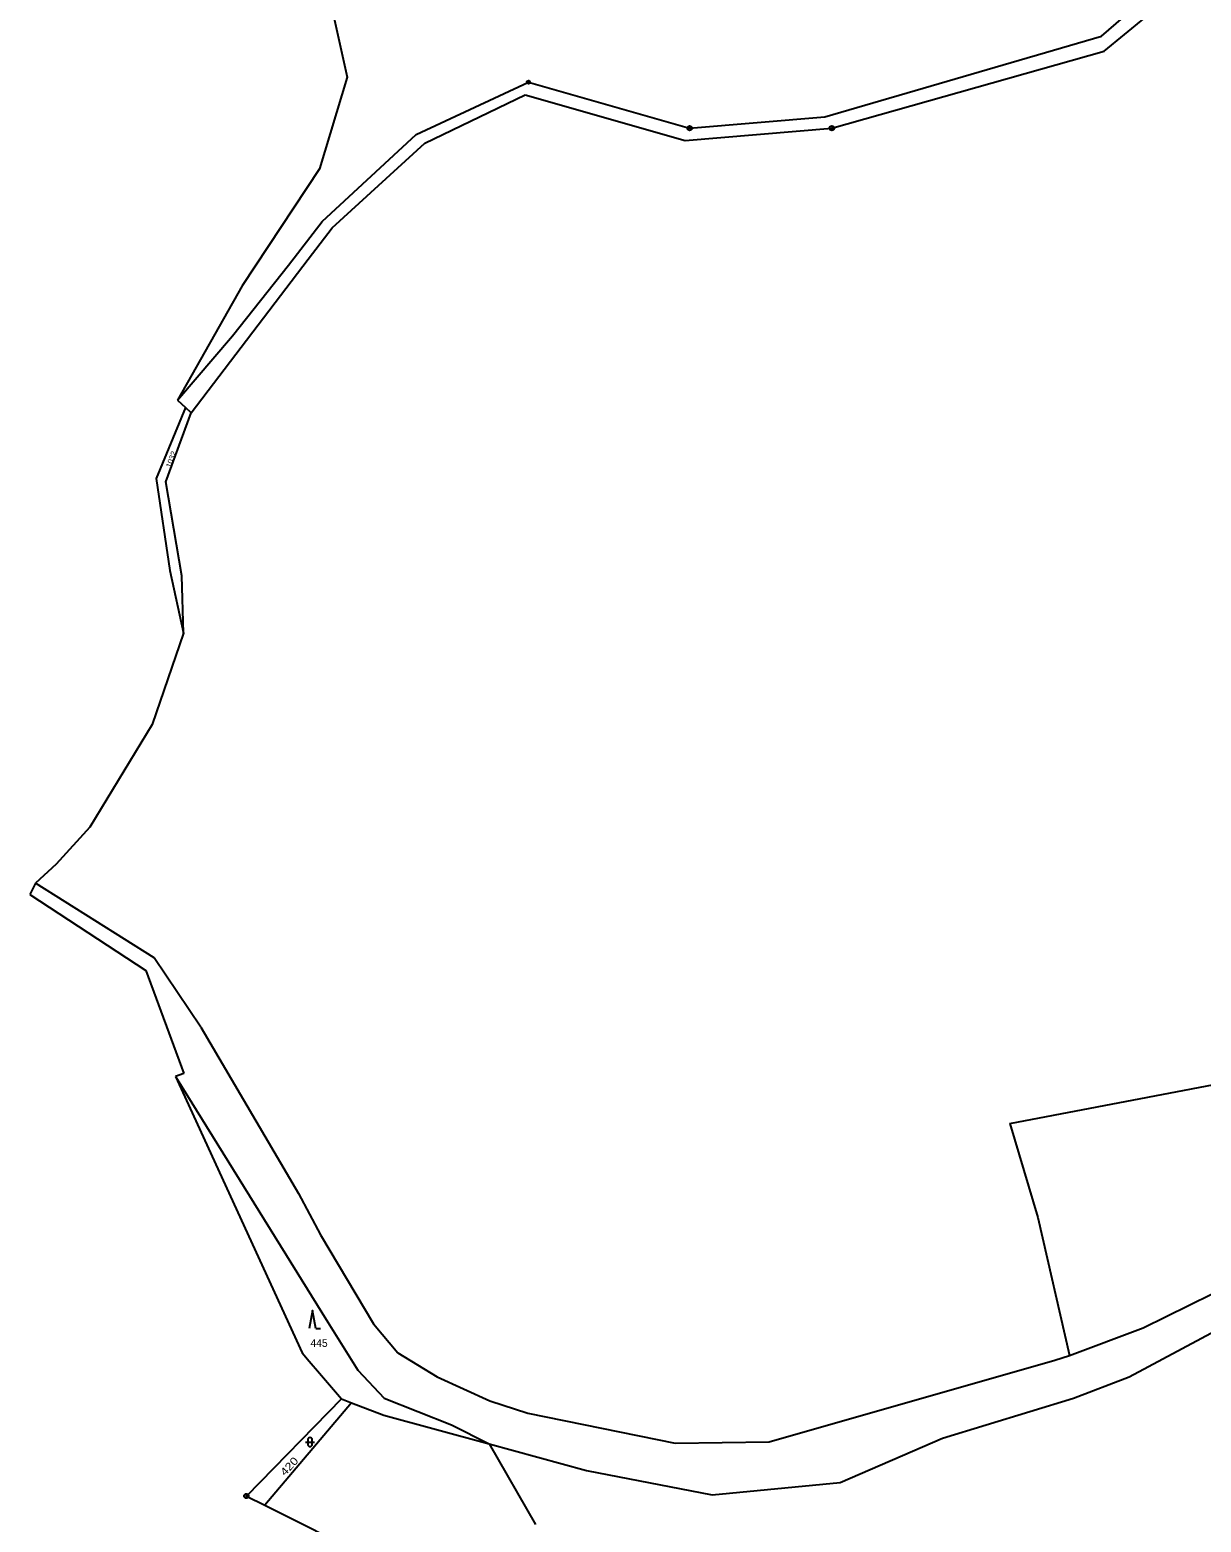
# Model space of a CAD drawing. Extents: x -744132 to -742433, y -984679 to -982287.
# Drawn here: x -743928.5 to -743670, y -984036.9 to -983707.4 of the extents above; entities that cross this region are included whole.
import ezdxf

# ---------------------------------------------------------------- set-up
doc = ezdxf.new("R2010")
doc.units = 0
doc.header["$LTSCALE"] = 0.68
for name, color, linetype, lineweight in [('1', 7, 'Continuous', 25), ('3', 7, 'Continuous', 25), ('8', 7, 'Continuous', 25)]:
    doc.layers.add(name, color=color, linetype=linetype, lineweight=lineweight)
doc.layers.add('2', color=7, linetype='Continuous')

msp = doc.modelspace()

# ---------------------------------------------------------------- linework, layer by layer
at = {"layer": '1'}
for p, q in [((-743691.96, -983708.83), (-743675.09, -983694.16)), ((-743863.09, -983697.13), (-743858.44, -983717.89)), ((-743691.4, -983712.12), (-743677.95, -983701.07)), ((-743753.05, -983726.63), (-743691.96, -983708.83)), ((-743751.49, -983729.12), (-743691.4, -983712.12)), ((-743858.44, -983717.89), (-743864.57, -983738.11)), ((-743843.22, -983730.49), (-743818.47, -983718.97)), ((-743818.47, -983718.97), (-743782.88, -983729.12)), ((-743841.32, -983732.45), (-743819.15, -983721.77)), ((-743819.15, -983721.77), (-743783.88, -983731.83)), ((-743782.88, -983729.12), (-743753.05, -983726.63)), ((-743863.99, -983749.75), (-743843.22, -983730.49)), ((-743783.88, -983731.83), (-743751.49, -983729.12)), ((-743861.8, -983751.15), (-743841.32, -983732.45)), ((-743864.57, -983738.11), (-743881.67, -983763.97)), ((-743871.43, -983759.35), (-743863.99, -983749.75)), ((-743867.08, -983758.06), (-743861.8, -983751.15)), ((-743892.87, -983791.95), (-743867.08, -983758.06)), ((-743883.77, -983774.96), (-743871.43, -983759.35)), ((-743881.67, -983763.97), (-743895.94, -983789.18)), ((-743895.94, -983789.18), (-743883.77, -983774.96)), ((-743894.18, -983790.79), (-743900.64, -983806.45)), ((-743895.94, -983789.18), (-743894.18, -983790.79)), ((-743892.87, -983791.95), (-743894.18, -983790.79)), ((-743898.46, -983807.23), (-743892.87, -983791.95)), ((-743900.64, -983806.45), (-743897.61, -983826.79)), ((-743894.96, -983827.99), (-743898.46, -983807.23)), ((-743897.61, -983826.79), (-743894.57, -983840.59)), ((-743894.57, -983840.59), (-743894.96, -983827.99)), ((-743894.57, -983840.59), (-743901.53, -983860.75)), ((-743901.53, -983860.75), (-743915.26, -983883.48)), ((-743915.26, -983883.48), (-743922.66, -983891.64)), ((-743922.66, -983891.64), (-743927.22, -983895.83)), ((-743927.22, -983895.83), (-743928.5, -983898.32)), ((-743901.08, -983912.29), (-743927.22, -983895.83)), ((-743928.5, -983898.32), (-743902.92, -983915.06)), ((-743890.76, -983927.58), (-743901.08, -983912.29)), ((-743902.92, -983915.06), (-743894.54, -983937.82)), ((-743890.76, -983927.58), (-743869.24, -983964.3)), ((-743894.54, -983937.82), (-743896.33, -983938.48)), ((-743896.33, -983938.48), (-743862.71, -983992.75)), ((-743896.33, -983938.48), (-743868.4, -983999.52)), ((-743712.18, -983948.85), (-743657.74, -983938.48)), ((-743712.18, -983948.85), (-743706.04, -983969.65)), ((-743869.24, -983964.3), (-743864.34, -983973.46)), ((-743706.04, -983969.65), (-743699.03, -984000.06)), ((-743864.34, -983973.46), (-743852.64, -983993.08)), ((-743682.75, -983994), (-743655.16, -983980.38)), ((-743685.87, -984004.83), (-743652.22, -983986.81)), ((-743862.71, -983992.75), (-743856.08, -984003.37)), ((-743852.64, -983993.08), (-743847.29, -983999.52)), ((-743699.03, -984000.06), (-743682.75, -983994)), ((-743868.4, -983999.52), (-743866.84, -984001.34)), ((-743866.84, -984001.34), (-743864.55, -984004.01)), ((-743847.29, -983999.52), (-743838.59, -984004.8)), ((-743765.34, -984019.15), (-743702.29, -984001.14)), ((-743702.29, -984001.14), (-743699.03, -984000.06)), ((-743864.55, -984004.01), (-743859.69, -984009.69)), ((-743856.08, -984003.37), (-743850.29, -984009.51)), ((-743838.59, -984004.8), (-743826.95, -984010.11)), ((-743698.19, -984009.54), (-743685.87, -984004.83)), ((-743859.69, -984009.69), (-743880.71, -984031.13)), ((-743857.49, -984010.54), (-743876.64, -984033.16)), ((-743859.69, -984009.69), (-743857.49, -984010.54)), ((-743857.49, -984010.54), (-743850.34, -984013.25)), ((-743850.29, -984009.51), (-743835.46, -984015.41)), ((-743826.95, -984010.11), (-743818.58, -984012.86)), ((-743727.1, -984018.32), (-743698.19, -984009.54)), ((-743850.34, -984013.25), (-743827.09, -984019.6)), ((-743818.58, -984012.86), (-743786.06, -984019.44)), ((-743835.46, -984015.41), (-743827.09, -984019.6)), ((-743827.09, -984019.6), (-743816.9, -984037.38)), ((-743827.09, -984019.6), (-743805.65, -984025.45)), ((-743786.06, -984019.44), (-743765.34, -984019.15)), ((-743749.65, -984028.17), (-743727.1, -984018.32)), ((-743805.65, -984025.45), (-743777.9, -984030.83)), ((-743880.71, -984031.13), (-743876.64, -984033.16)), ((-743777.9, -984030.83), (-743749.65, -984028.17)), ((-743876.64, -984033.16), (-743813.8, -984064.5))]:
    msp.add_line(p, q, dxfattribs=at)
at = {"layer": '3'}
for p, q in [((-743865.35, -983994.16), (-743864.354, -983994.16)), ((-743867.681, -984019.221), (-743865.679, -984019.221)), ((-743867.181, -984018.721), (-743867.181, -984019.722)), ((-743866.179, -984019.722), (-743866.179, -984018.721))]:
    msp.add_line(p, q, dxfattribs=at)
msp.add_lwpolyline([(-743865.35, -983994.16), (-743866.1, -983990.16), (-743866.85, -983994.16)], dxfattribs=at)
for centre, start, end in [((-743866.68, -984018.7209), 0, 180), ((-743866.68, -984019.7209), 180, 359.98789)]:
    msp.add_arc(centre, 0.5, start, end, dxfattribs=at)
at = {"layer": '8'}
for centre, radius in [((-743818.47, -983718.9699), 0.35), ((-743818.47, -983718.9699), 0.0212), ((-743782.88, -983729.1199), 0.5), ((-743782.88, -983729.1199), 0.0303), ((-743751.49, -983729.1199), 0.5), ((-743751.49, -983729.1199), 0.0303), ((-743880.71, -984031.1299), 0.5), ((-743880.71, -984031.1299), 0.0303)]:
    msp.add_circle(centre, radius, dxfattribs=at)

# ---------------------------------------------------------------- texts
at = {"layer": '2'}
for s, height, rotation, width, p in [('1032', 1.19, 70, 1.05, (-743897.38, -983804.201)), ('420', 1.7, 47, 1.2, (-743872.189, -984026.809))]:
    msp.add_text(s, height=height, rotation=rotation, dxfattribs=dict(at, width=width)).set_placement(p)
msp.add_text('445', height=1.7, dxfattribs=at).set_placement((-743866.57, -983998.195))

doc.saveas('drawing.dxf')
